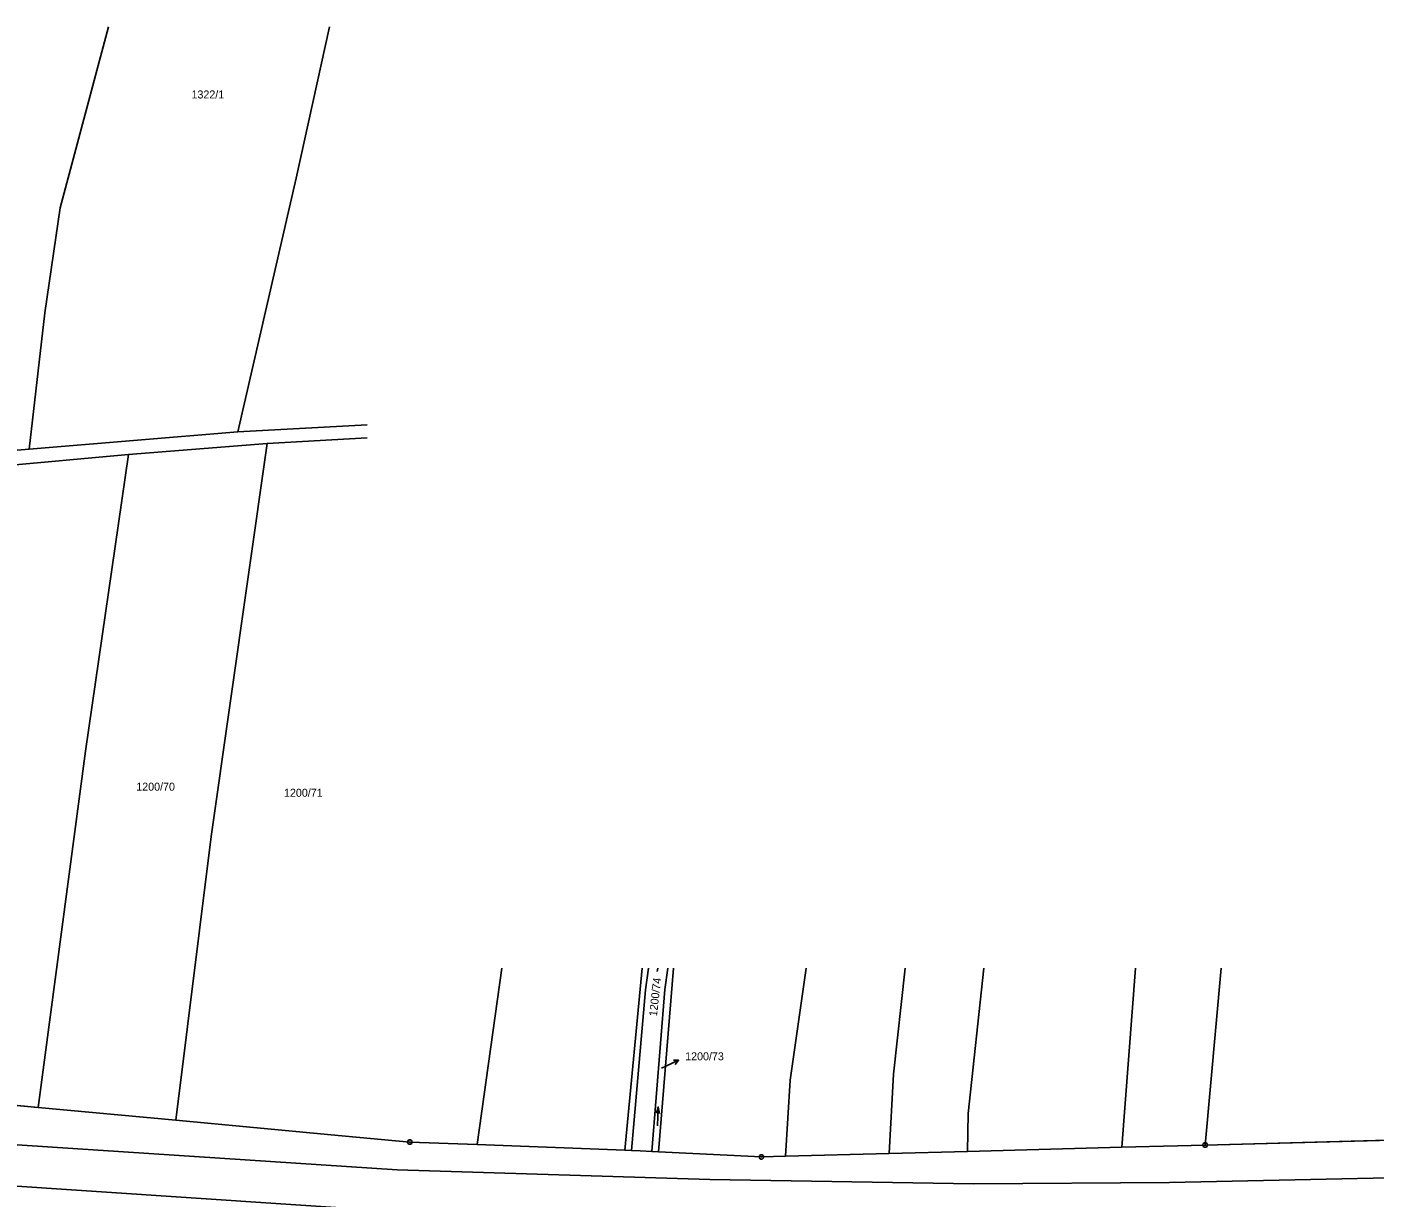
# Model space of a CAD drawing. Extents: x -777309 to -774195, y -1144706 to -1143600.
# Drawn here: x -776672.3 to -776386.1, y -1143848.6 to -1143600 of the extents above; entities that cross this region are included whole.
import ezdxf

# ---------------------------------------------------------------- set-up
doc = ezdxf.new("R2010")
doc.units = 0
for name, color, linetype in [('1', 7, 'Continuous'), ('11', 7, 'Continuous'), ('2', 7, 'Continuous'), ('3', 7, 'Continuous'), ('4', 7, 'Continuous'), ('7', 7, 'Continuous'), ('8', 7, 'Continuous')]:
    doc.layers.add(name, color=color, linetype=linetype)

msp = doc.modelspace()

# ---------------------------------------------------------------- linework, layer by layer
at = {"layer": '1'}
for p, q in [((-776665.18, -1143638.43), (-776654.94, -1143600)), ((-776607.97, -1143600), (-776615.06, -1143632.12)), ((-776627.48, -1143686.05), (-776615.06, -1143632.12)), ((-776665.18, -1143638.43), (-776668.44, -1143660.72)), ((-776668.44, -1143660.72), (-776671.82, -1143689.69)), ((-776627.48, -1143686.05), (-776671.82, -1143689.69)), ((-776627.48, -1143686.05), (-776600, -1143684.54)), ((-776695.6, -1143691.74), (-776671.82, -1143689.69)), ((-776650.69, -1143690.83), (-776621.25, -1143688.51)), ((-776633.12, -1143771.99), (-776621.25, -1143688.51)), ((-776621.25, -1143688.51), (-776600, -1143687.34)), ((-776695.8, -1143695), (-776650.69, -1143690.83)), ((-776659.83, -1143753.85), (-776650.69, -1143690.83)), ((-776659.83, -1143753.85), (-776669.89, -1143829.58)), ((-776633.12, -1143771.99), (-776640.68, -1143832.31)), ((-776571.41, -1143800), (-776576.67, -1143837.48)), ((-776545.27, -1143838.65), (-776541.56, -1143800)), ((-776540.25, -1143800), (-776540.87, -1143804.61)), ((-776538.12, -1143839.04), (-776534.92, -1143800)), ((-776536.12, -1143800), (-776536.77, -1143804.52)), ((-776506.74, -1143800), (-776510.15, -1143823.79)), ((-776485.72, -1143800), (-776488.2, -1143822.51)), ((-776469, -1143800), (-776472.33, -1143830.9)), ((-776439.72, -1143838.05), (-776436.81, -1143800)), ((-776421.99, -1143837.57), (-776418.59, -1143800)), ((-776540.87, -1143804.61), (-776543.86, -1143838.73)), ((-776536.77, -1143804.52), (-776539.57, -1143838.96)), ((-776511.15, -1143839.97), (-776510.15, -1143823.79)), ((-776488.2, -1143822.51), (-776489.11, -1143839.38)), ((-776669.89, -1143829.58), (-776712.16, -1143825.63)), ((-776640.68, -1143832.31), (-776669.89, -1143829.58)), ((-776607.67, -1143835.39), (-776640.68, -1143832.31)), ((-776472.47, -1143838.93), (-776472.33, -1143830.9)), ((-776590.95, -1143836.95), (-776607.67, -1143835.39)), ((-776421.99, -1143837.57), (-776347.03, -1143835.55)), ((-776576.67, -1143837.48), (-776590.95, -1143836.95)), ((-776545.27, -1143838.65), (-776576.67, -1143837.48)), ((-776543.86, -1143838.73), (-776545.27, -1143838.65)), ((-776542.02, -1143838.83), (-776543.86, -1143838.73)), ((-776539.57, -1143838.96), (-776542.02, -1143838.83)), ((-776538.12, -1143839.04), (-776539.57, -1143838.96)), ((-776489.11, -1143839.38), (-776472.47, -1143838.93)), ((-776472.47, -1143838.93), (-776439.72, -1143838.05)), ((-776439.72, -1143838.05), (-776421.99, -1143837.57)), ((-776516.26, -1143840.11), (-776538.12, -1143839.04)), ((-776516.26, -1143840.11), (-776511.15, -1143839.97)), ((-776511.15, -1143839.97), (-776489.11, -1143839.38))]:
    msp.add_line(p, q, dxfattribs=at)
at = {"layer": '11'}
for points in [[(-776712.16, -1143825.63), (-776669.89, -1143829.58), (-776640.68, -1143832.31), (-776607.67, -1143835.39), (-776590.95, -1143836.95), (-776576.67, -1143837.48), (-776545.27, -1143838.65), (-776541.56, -1143800)], [(-776534.92, -1143800), (-776538.12, -1143839.04), (-776516.26, -1143840.11), (-776511.15, -1143839.97), (-776489.11, -1143839.38), (-776472.47, -1143838.93), (-776439.72, -1143838.05), (-776421.99, -1143837.57), (-776347.03, -1143835.55), (-776311.1, -1143834.59), (-776287.47, -1143833.95), (-776268.92, -1143833.45), (-776230.55, -1143834.21)]]:
    msp.add_lwpolyline(points, dxfattribs=at)
at = {"layer": '3'}
for p, q in [((-776538.38, -1143800.71), (-776538.28, -1143800)), ((-776538.33, -1143833.51), (-776538.19, -1143829.49))]:
    msp.add_line(p, q, dxfattribs=at)
msp.add_lwpolyline([(-776538.57, -1143830.82), (-776538.19, -1143829.49), (-776537.9, -1143830.84)], dxfattribs=at)
at = {"layer": '4'}
for p, q in [((-776693.94, -1143836.23), (-776593.63, -1143842.83)), ((-776527.2, -1143844.89), (-776593.63, -1143842.83)), ((-776289.89, -1143842.57), (-776429.58, -1143845.53)), ((-776694.77, -1143844.97), (-776596.12, -1143851.55)), ((-776527.2, -1143844.89), (-776471.18, -1143845.83)), ((-776429.58, -1143845.53), (-776471.18, -1143845.83))]:
    msp.add_line(p, q, dxfattribs=at)
at = {"layer": '7'}
for p in [(-776537.49, -1143821.26), (-776533.85, -1143819.57)]:
    msp.add_line(p, (-776536.57, -1143820.83), dxfattribs=at)
msp.add_lwpolyline([(-776534.97, -1143819.53), (-776533.85, -1143819.57), (-776534.55, -1143820.44)], dxfattribs=at)
at = {"layer": '8'}
for p, q in [((-776591.07, -1143836.95), (-776590.83, -1143836.95)), ((-776422.11, -1143837.57), (-776421.87, -1143837.57)), ((-776516.38, -1143840.11), (-776516.14, -1143840.11))]:
    msp.add_line(p, q, dxfattribs=at)
for points in [[(-776590.8, -1143836.47), (-776590.55, -1143836.65), (-776590.45, -1143836.94), (-776590.55, -1143837.23), (-776590.8, -1143837.41), (-776591.11, -1143837.41), (-776591.36, -1143837.23), (-776591.46, -1143836.94), (-776591.36, -1143836.65), (-776591.11, -1143836.47)], [(-776421.84, -1143837.09), (-776421.59, -1143837.27), (-776421.49, -1143837.56), (-776421.59, -1143837.85), (-776421.84, -1143838.03), (-776422.15, -1143838.03), (-776422.4, -1143837.85), (-776422.5, -1143837.56), (-776422.4, -1143837.27), (-776422.15, -1143837.09)], [(-776516.11, -1143839.63), (-776515.86, -1143839.81), (-776515.76, -1143840.1), (-776515.86, -1143840.39), (-776516.11, -1143840.57), (-776516.42, -1143840.57), (-776516.67, -1143840.39), (-776516.77, -1143840.1), (-776516.67, -1143839.81), (-776516.42, -1143839.63)]]:
    msp.add_lwpolyline(points, close=True, dxfattribs=at)

# ---------------------------------------------------------------- texts
at = {"layer": '2'}
for s, height, p in [('1322/1', 1.7, (-776637.32, -1143615.2)), ('1200/70', 1.7, (-776649.05, -1143762.28)), ('1200/71', 1.7, (-776617.67, -1143763.57)), ('1200/73', 0.1, (-776537.47, -1143821.26))]:
    msp.add_text(s, height=height, dxfattribs=at).set_placement(p)
msp.add_text('1200/74', height=1.7, rotation=83.5372, dxfattribs=at).set_placement((-776538.46, -1143810.29))
at = {"layer": '7'}
msp.add_text('1200/73', height=1.7, dxfattribs=at).set_placement((-776532.46, -1143819.57))

doc.saveas('drawing.dxf')
